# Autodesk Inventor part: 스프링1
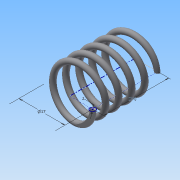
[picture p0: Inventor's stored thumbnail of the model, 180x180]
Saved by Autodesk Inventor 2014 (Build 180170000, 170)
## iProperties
Created: 2016-01
Part Number: 스프링1
Material: 강철, 탄소
Document SubType Name: Modeling
Designer: Administrator
Density: 7.87 g/cm^3
Appearance: 반연마
Mass: 6.46669 g
Surface Area: 16.7182 cm^2
Volume: 0.821689 cm^3
Author: Administrator
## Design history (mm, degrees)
sketch "스케치1"
  geometry: L1 (0, 0)-(8.5, 0); L2 (8.5, 0)-(8.5, 20.5); L3 (8.5, 20.5)-(0, 20.5); L4 (0, 20.5)-(0, 0); C1 r 1 at (8.5, 0)
  constraints: 8 end point, 2 parallel, 1 centre point, 1 coincident, 1 horizontal, 1 perpendicular
  dimensions: "d0" = 17 diameter of L2 L4; "d1" = 20.5 distance of L1.end L2.end (derived); "d2" = 2 diameter of C1
feature "코일1" sketch "스케치1" pitch "d3" = 10; turns "d5" = 5; dims "d4" = 20.5 (= d1), "d6" = 0, angle "d7" = 90 deg, angle "d8" = 90 deg, "d9" = 0, "d10" = 0
node "작업 평면2"
  node "작업 평면1"
sketch "스케치2"
  geometry: L1 (-9.5, 0)-(-7.5, 0) reference; 1 further point
  constraints: 1 horizontal alignment
extrude "돌출1" cut sketch "스케치2" stored distance "d13" = 10; taper "d14" = 0 deg
sketch "스케치3"
  geometry: L1 (-7.5, 0)-(-9.5, 0) reference; 1 further point
  constraints: 1 horizontal alignment
extrude "돌출2" cut sketch "스케치3" stored distance "d15" = 10; taper "d16" = 0 deg
node "솔리드1"
node "절단 모서리 투영1"
node "절단 모서리 투영2"
other parameters: "d11" = 0, "d12" = 20.5 (= d1)
